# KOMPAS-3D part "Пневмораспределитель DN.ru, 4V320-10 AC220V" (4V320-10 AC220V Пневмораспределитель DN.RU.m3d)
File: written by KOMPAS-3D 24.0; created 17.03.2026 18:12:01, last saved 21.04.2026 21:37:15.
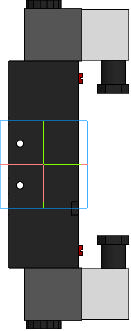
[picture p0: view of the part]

Document properties: Автор: R2D2; Полное имя файла: E:\Работа\Зайцев\Аксессуары для пневмоприводов\Пневмораспределители DN.ru\4V320 AC220V Пневмораспределитель DN.RU\4V320-10 AC220V Пневмораспределитель DN.RU\4V320-10 AC220V Пневмораспределитель DN.RU.m3d

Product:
- Part/product: Пневмораспределитель DN.ru  | designation 4V320-10 AC220V
    Масса: 1.2
    Раздел спецификации: Прочие изделия
    Примечание: D290-00335

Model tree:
1. Операция без истории:1

Expressions: 4V320-10 AC220V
